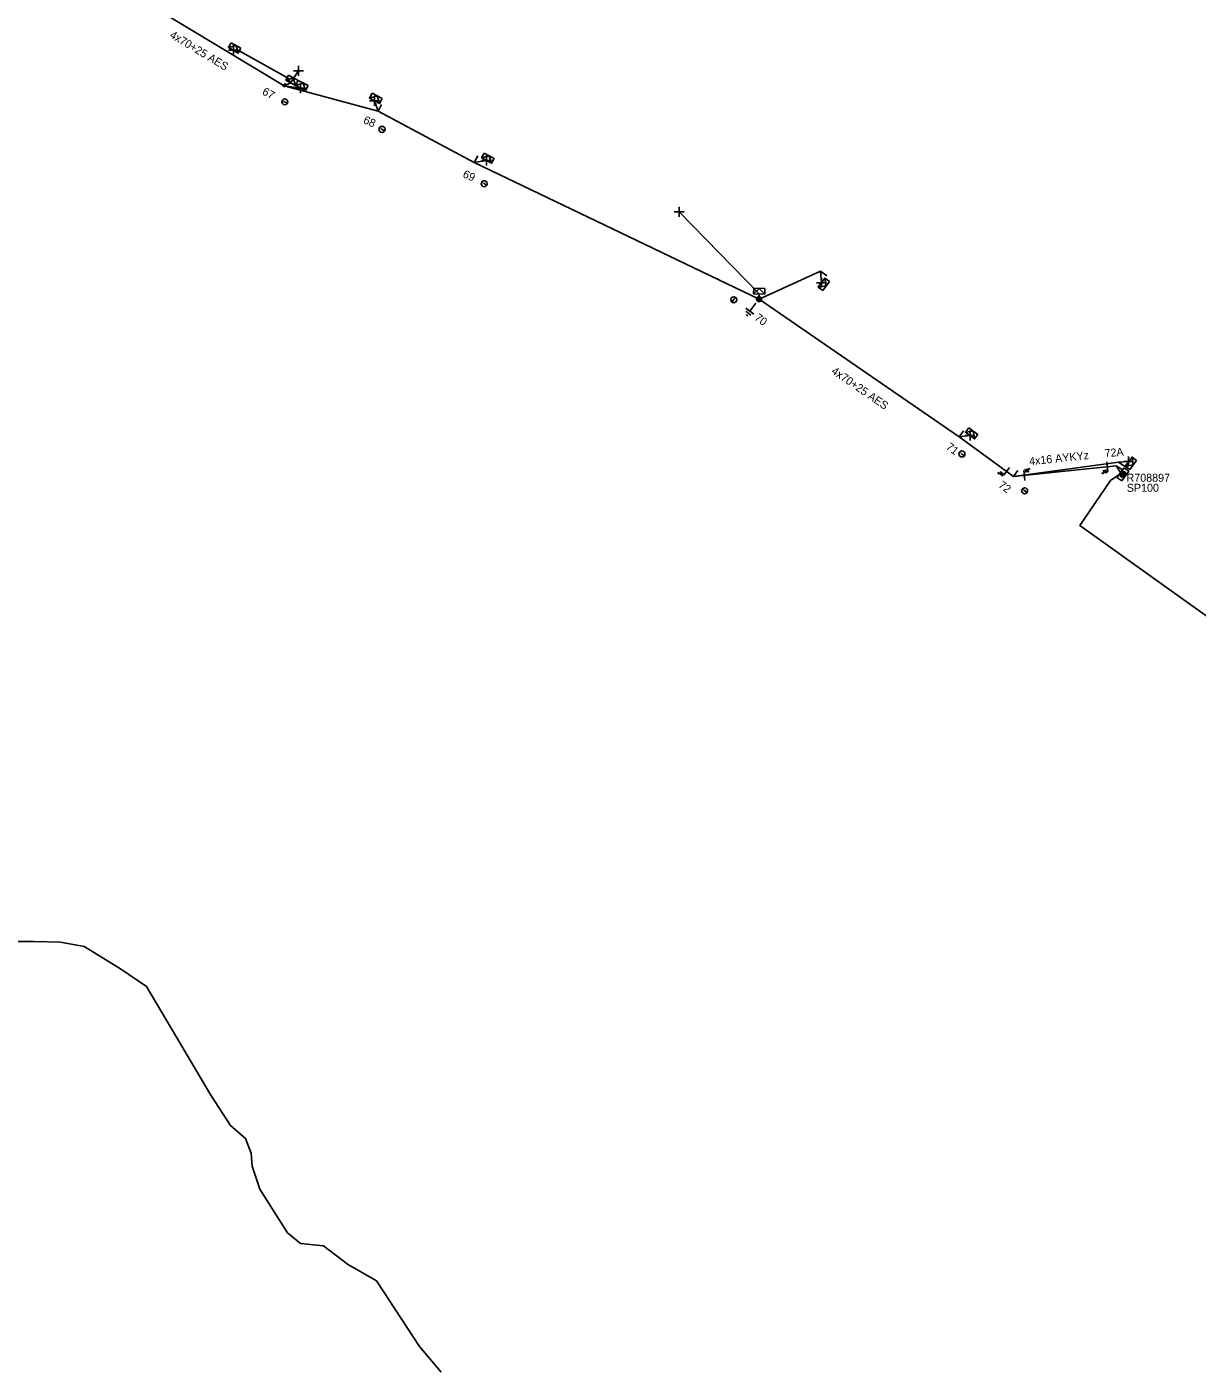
# Model space of a CAD drawing. Extents: x -540466 to -537383, y -1184038 to -1179972.
# Drawn here: x -537707.7 to -537561.4, y -1180709.3 to -1180542.1 of the extents above; entities that cross this region are included whole.
import ezdxf

# ---------------------------------------------------------------- set-up
doc = ezdxf.new("R2010")
doc.units = 0
for name, color, linetype in [('Vrstva 1', 7, 'Continuous'), ('Vrstva 10', 7, 'Continuous'), ('Vrstva 13', 7, 'Continuous'), ('Vrstva 14', 7, 'Continuous'), ('Vrstva 15', 7, 'Continuous'), ('Vrstva 18', 7, 'Continuous'), ('Vrstva 2', 7, 'Continuous'), ('Vrstva 28', 7, 'Continuous'), ('Vrstva 29', 7, 'Continuous'), ('Vrstva 30', 7, 'Continuous'), ('Vrstva 31', 7, 'Continuous'), ('Vrstva 34', 7, 'Continuous'), ('Vrstva 36', 7, 'Continuous'), ('Vrstva 4', 7, 'Continuous'), ('Vrstva 5', 7, 'Continuous'), ('Vrstva 50', 7, 'Continuous'), ('Vrstva 51', 7, 'Continuous'), ('Vrstva 52', 7, 'Continuous'), ('Vrstva 53', 7, 'Continuous'), ('Vrstva 54', 7, 'Continuous'), ('Vrstva 59', 7, 'Continuous'), ('Vrstva 8', 7, 'Continuous'), ('Vrstva 9', 7, 'Continuous')]:
    doc.layers.add(name, color=color, linetype=linetype)

# ---------------------------------------------------------------- blocks, each defined once
blk = doc.blocks.new('NN440')
at = {"layer": 'Vrstva 2'}
for points in [[(0.63, 0), (0.63, 0.06), (0.62, 0.13), (0.6, 0.19), (0.58, 0.25), (0.55, 0.31), (0.51, 0.37), (0.47, 0.42), (0.42, 0.46), (0.37, 0.51), (0.32, 0.54), (0.26, 0.57), (0.2, 0.59), (0.13, 0.61), (0.07, 0.62), (0, 0.63), (-0.06, 0.62), (-0.13, 0.61), (-0.19, 0.59), (-0.26, 0.57), (-0.31, 0.54), (-0.37, 0.51), (-0.42, 0.46), (-0.47, 0.42), (-0.51, 0.37), (-0.54, 0.31), (-0.57, 0.25), (-0.6, 0.19), (-0.62, 0.13), (-0.63, 0.06), (-0.63, 0), (-0.63, -0.07), (-0.62, -0.14), (-0.6, -0.2), (-0.57, -0.26), (-0.54, -0.32), (-0.51, -0.37), (-0.47, -0.43), (-0.42, -0.47), (-0.37, -0.51), (-0.31, -0.55), (-0.26, -0.58), (-0.19, -0.6), (-0.13, -0.62), (-0.06, -0.63), (0, -0.63), (0.07, -0.63), (0.13, -0.62), (0.2, -0.6), (0.26, -0.58), (0.32, -0.55), (0.37, -0.51), (0.42, -0.47), (0.47, -0.43), (0.51, -0.37), (0.55, -0.32), (0.58, -0.26), (0.6, -0.2), (0.62, -0.14), (0.63, -0.07), (0.63, 0)], [(-0.63, 0), (0.63, 0)], [(-0.6, -0.18), (0.57, -0.18)], [(-0.51, -0.32), (0.5, -0.32)], [(-0.37, -0.47), (0.35, -0.47)]]:
    blk.add_lwpolyline(points, dxfattribs=at)
blk = doc.blocks.new('NN840')
at = {"layer": 'Vrstva 15'}
for points in [[(0, 0.62), (0, -0.63)], [(-0.75, -0.71), (-0.75, -0.66)], [(-0.73, -0.76), (-0.75, -0.71)], [(-0.66, -0.8), (-0.73, -0.76)], [(-0.63, -0.8), (-0.66, -0.8)], [(-0.56, -0.76), (-0.63, -0.8)], [(-0.54, -0.71), (-0.56, -0.76)], [(-0.54, -0.38), (-0.54, -0.71)], [(-0.33, -0.38), (-0.33, -0.8)], [(-0.33, -0.64), (-0.13, -0.38)], [(-0.26, -0.56), (-0.09, -0.8)]]:
    blk.add_lwpolyline(points, dxfattribs=at)
blk = doc.blocks.new('NN770')
at = {"layer": 'Vrstva 10'}
for p, q in [((0, 0.19), (0, 0.26)), ((0, -0.28), (0, 0.11))]:
    blk.add_line(p, q, dxfattribs=at)
blk.add_circle((0, -0.01), 0.375, dxfattribs=at)
blk = doc.blocks.new('NN800')
at = {"layer": 'Vrstva 1'}
for points in [[(-0.44, 0.44), (0.44, -0.44)], [(-0.44, -0.44), (0.44, 0.44)]]:
    blk.add_lwpolyline(points, dxfattribs=at)
blk = doc.blocks.new('NN620')
at = {"layer": 'Vrstva 8'}
for points in [[(0.75, 0), (-0.75, 0)], [(-0.75, 0), (-0.75, -0.75)], [(0.75, -0.75), (0.75, 0)], [(-0.75, -0.75), (0.75, -0.75)], [(0.37, -0.18), (-0.38, -0.18)], [(-0.38, -0.18), (-0.38, -0.56)], [(-0.38, -0.56), (0.37, -0.56)], [(0.32, -0.23), (-0.33, -0.23)], [(-0.33, -0.23), (-0.33, -0.51)], [(-0.33, -0.51), (0.32, -0.51)], [(0.27, -0.27), (-0.28, -0.27)], [(-0.28, -0.27), (-0.28, -0.46)], [(-0.28, -0.46), (0.27, -0.46)], [(0.23, -0.32), (-0.23, -0.32)], [(-0.23, -0.32), (-0.23, -0.42)], [(-0.23, -0.42), (0.23, -0.42)], [(-0.19, -0.37), (0.19, -0.37)], [(0.23, -0.42), (0.23, -0.32)], [(0.27, -0.46), (0.27, -0.27)], [(0.32, -0.51), (0.32, -0.23)], [(0.37, -0.56), (0.37, -0.18)]]:
    blk.add_lwpolyline(points, dxfattribs=at)
blk = doc.blocks.new('NN630')
at = {"layer": 'Vrstva 9'}
for points in [[(0, -0.7), (-0.7, 0)], [(-0.7, -0.7), (-0.7, 0), (0.7, 0), (0.7, -0.7)], [(-0.7, -0.7), (0.7, -0.7)], [(0, -0.7), (0.7, 0)]]:
    blk.add_lwpolyline(points, dxfattribs=at)
blk = doc.blocks.new('NN810')
at = {"layer": 'Vrstva 14'}
for points in [[(0, -0.64), (0, -1.89)], [(0.63, -1.89), (-0.62, -1.89)], [(0.39, -2.2), (-0.4, -2.2)], [(0, -2.52), (-0.12, -2.52)], [(0.14, -2.52), (0, -2.52)]]:
    blk.add_lwpolyline(points, dxfattribs=at)
blk = doc.blocks.new('NN500')
at = {"layer": 'Vrstva 2'}
for points in [[(0, -0.24), (0.02, -0.23), (0.05, -0.23), (0.07, -0.22), (0.09, -0.22), (0.12, -0.2), (0.14, -0.19), (0.16, -0.18), (0.17, -0.16), (0.19, -0.14), (0.2, -0.12), (0.21, -0.1), (0.22, -0.07), (0.23, -0.05), (0.23, -0.02), (0.23, 0), (0.23, 0.02), (0.23, 0.05), (0.22, 0.07), (0.21, 0.1), (0.2, 0.12), (0.19, 0.14), (0.17, 0.16), (0.16, 0.17), (0.14, 0.19), (0.12, 0.2), (0.09, 0.21), (0.07, 0.22), (0.05, 0.23), (0.02, 0.23), (0, 0.23), (-0.03, 0.23), (-0.05, 0.23), (-0.07, 0.22), (-0.1, 0.21), (-0.12, 0.2), (-0.14, 0.19), (-0.16, 0.17), (-0.18, 0.16), (-0.19, 0.14), (-0.2, 0.12), (-0.22, 0.1), (-0.22, 0.07), (-0.23, 0.05), (-0.23, 0.02), (-0.24, 0), (-0.23, -0.02), (-0.23, -0.05), (-0.22, -0.07), (-0.22, -0.1), (-0.2, -0.12), (-0.19, -0.14), (-0.18, -0.16), (-0.16, -0.18), (-0.14, -0.19), (-0.12, -0.2), (-0.1, -0.22), (-0.07, -0.22), (-0.05, -0.23), (-0.03, -0.23), (0, -0.24)], [(0, -0.24), (0.02, -0.23), (0.05, -0.23), (0.07, -0.22), (0.09, -0.22), (0.12, -0.2), (0.14, -0.19), (0.16, -0.18), (0.17, -0.16), (0.19, -0.14), (0.2, -0.12), (0.21, -0.1), (0.22, -0.07), (0.23, -0.05), (0.23, -0.02), (0.23, 0), (0.23, 0.02), (0.23, 0.05), (0.22, 0.07), (0.21, 0.1), (0.2, 0.12), (0.19, 0.14), (0.17, 0.16), (0.16, 0.17), (0.14, 0.19), (0.12, 0.2), (0.09, 0.21), (0.07, 0.22), (0.05, 0.23), (0.02, 0.23), (0, 0.23), (-0.03, 0.23), (-0.05, 0.23), (-0.07, 0.22), (-0.1, 0.21), (-0.12, 0.2), (-0.14, 0.19), (-0.16, 0.17), (-0.18, 0.16), (-0.19, 0.14), (-0.2, 0.12), (-0.22, 0.1), (-0.22, 0.07), (-0.23, 0.05), (-0.23, 0.02), (-0.24, 0), (-0.23, -0.02), (-0.23, -0.05), (-0.22, -0.07), (-0.22, -0.1), (-0.2, -0.12), (-0.19, -0.14), (-0.18, -0.16), (-0.16, -0.18), (-0.14, -0.19), (-0.12, -0.2), (-0.1, -0.22), (-0.07, -0.22), (-0.05, -0.23), (-0.03, -0.23), (0, -0.24)], [(0, -0.21), (0.02, -0.2), (0.04, -0.2), (0.06, -0.2), (0.08, -0.19), (0.1, -0.18), (0.12, -0.17), (0.14, -0.15), (0.15, -0.14), (0.16, -0.12), (0.18, -0.1), (0.19, -0.08), (0.19, -0.06), (0.2, -0.04), (0.2, -0.02), (0.2, 0), (0.2, 0.02), (0.2, 0.04), (0.19, 0.06), (0.19, 0.08), (0.18, 0.1), (0.16, 0.12), (0.15, 0.14), (0.14, 0.15), (0.12, 0.17), (0.1, 0.18), (0.08, 0.19), (0.06, 0.19), (0.04, 0.2), (0.02, 0.2), (0, 0.2), (-0.02, 0.2), (-0.04, 0.2), (-0.06, 0.19), (-0.08, 0.19), (-0.1, 0.18), (-0.12, 0.17), (-0.14, 0.15), (-0.15, 0.14), (-0.17, 0.12), (-0.18, 0.1), (-0.19, 0.08), (-0.2, 0.06), (-0.2, 0.04), (-0.21, 0.02), (-0.21, 0), (-0.21, -0.02), (-0.2, -0.04), (-0.2, -0.06), (-0.19, -0.08), (-0.18, -0.1), (-0.17, -0.12), (-0.15, -0.14), (-0.14, -0.15), (-0.12, -0.17), (-0.1, -0.18), (-0.08, -0.19), (-0.06, -0.2), (-0.04, -0.2), (-0.02, -0.2), (0, -0.21)], [(0, -0.18), (0.02, -0.18), (0.04, -0.17), (0.05, -0.17), (0.07, -0.16), (0.09, -0.15), (0.1, -0.14), (0.12, -0.13), (0.13, -0.12), (0.14, -0.1), (0.15, -0.09), (0.16, -0.07), (0.17, -0.05), (0.17, -0.04), (0.17, -0.02), (0.17, 0), (0.17, 0.02), (0.17, 0.04), (0.17, 0.05), (0.16, 0.07), (0.15, 0.09), (0.14, 0.1), (0.13, 0.12), (0.12, 0.13), (0.1, 0.14), (0.09, 0.15), (0.07, 0.16), (0.05, 0.17), (0.04, 0.17), (0.02, 0.17), (0, 0.18), (-0.02, 0.17), (-0.04, 0.17), (-0.06, 0.17), (-0.07, 0.16), (-0.09, 0.15), (-0.1, 0.14), (-0.12, 0.13), (-0.13, 0.12), (-0.14, 0.1), (-0.15, 0.09), (-0.16, 0.07), (-0.17, 0.05), (-0.17, 0.04), (-0.18, 0.02), (-0.18, 0), (-0.18, -0.02), (-0.17, -0.04), (-0.17, -0.05), (-0.16, -0.07), (-0.15, -0.09), (-0.14, -0.1), (-0.13, -0.12), (-0.12, -0.13), (-0.1, -0.14), (-0.09, -0.15), (-0.07, -0.16), (-0.06, -0.17), (-0.04, -0.17), (-0.02, -0.18), (0, -0.18)], [(0, -0.15), (0.01, -0.15), (0.03, -0.14), (0.04, -0.14), (0.06, -0.13), (0.07, -0.13), (0.08, -0.12), (0.1, -0.11), (0.11, -0.1), (0.12, -0.09), (0.13, -0.07), (0.13, -0.06), (0.14, -0.05), (0.14, -0.03), (0.14, -0.02), (0.14, 0), (0.14, 0.01), (0.14, 0.03), (0.14, 0.04), (0.13, 0.06), (0.13, 0.07), (0.12, 0.09), (0.11, 0.1), (0.1, 0.11), (0.08, 0.12), (0.07, 0.13), (0.06, 0.13), (0.04, 0.14), (0.03, 0.14), (0.01, 0.14), (0, 0.15), (-0.02, 0.14), (-0.03, 0.14), (-0.05, 0.14), (-0.06, 0.13), (-0.07, 0.13), (-0.09, 0.12), (-0.1, 0.11), (-0.11, 0.1), (-0.12, 0.09), (-0.13, 0.07), (-0.13, 0.06), (-0.14, 0.04), (-0.14, 0.03), (-0.15, 0.01), (-0.15, 0), (-0.15, -0.02), (-0.14, -0.03), (-0.14, -0.05), (-0.13, -0.06), (-0.13, -0.07), (-0.12, -0.09), (-0.11, -0.1), (-0.1, -0.11), (-0.09, -0.12), (-0.07, -0.13), (-0.06, -0.13), (-0.05, -0.14), (-0.03, -0.14), (-0.02, -0.15), (0, -0.15)], [(0, -0.12), (0.01, -0.12), (0.02, -0.11), (0.03, -0.11), (0.05, -0.11), (0.06, -0.1), (0.07, -0.09), (0.08, -0.09), (0.09, -0.08), (0.09, -0.07), (0.1, -0.06), (0.11, -0.05), (0.11, -0.04), (0.11, -0.02), (0.11, -0.01), (0.12, 0), (0.11, 0.01), (0.11, 0.02), (0.11, 0.04), (0.11, 0.05), (0.1, 0.06), (0.09, 0.07), (0.09, 0.08), (0.08, 0.09), (0.07, 0.09), (0.06, 0.1), (0.05, 0.11), (0.03, 0.11), (0.02, 0.11), (0.01, 0.12), (0, 0.12), (-0.01, 0.12), (-0.03, 0.11), (-0.04, 0.11), (-0.05, 0.11), (-0.06, 0.1), (-0.07, 0.09), (-0.08, 0.09), (-0.09, 0.08), (-0.1, 0.07), (-0.1, 0.06), (-0.11, 0.05), (-0.11, 0.04), (-0.12, 0.02), (-0.12, 0.01), (-0.12, 0), (-0.12, -0.01), (-0.12, -0.02), (-0.11, -0.04), (-0.11, -0.05), (-0.1, -0.06), (-0.1, -0.07), (-0.09, -0.08), (-0.08, -0.09), (-0.07, -0.09), (-0.06, -0.1), (-0.05, -0.11), (-0.04, -0.11), (-0.03, -0.11), (-0.01, -0.12), (0, -0.12)], [(0, -0.09), (0.01, -0.09), (0.02, -0.09), (0.03, -0.08), (0.03, -0.08), (0.04, -0.08), (0.05, -0.07), (0.06, -0.07), (0.06, -0.06), (0.07, -0.05), (0.07, -0.04), (0.08, -0.04), (0.08, -0.03), (0.08, -0.02), (0.09, -0.01), (0.09, 0), (0.09, 0.01), (0.08, 0.02), (0.08, 0.03), (0.08, 0.03), (0.07, 0.04), (0.07, 0.05), (0.06, 0.06), (0.06, 0.06), (0.05, 0.07), (0.04, 0.07), (0.03, 0.08), (0.03, 0.08), (0.02, 0.08), (0.01, 0.09), (0, 0.09), (-0.01, 0.09), (-0.02, 0.08), (-0.03, 0.08), (-0.04, 0.08), (-0.04, 0.07), (-0.05, 0.07), (-0.06, 0.06), (-0.07, 0.06), (-0.07, 0.05), (-0.08, 0.04), (-0.08, 0.03), (-0.08, 0.03), (-0.09, 0.02), (-0.09, 0.01), (-0.09, 0), (-0.09, -0.01), (-0.09, -0.02), (-0.08, -0.03), (-0.08, -0.04), (-0.08, -0.04), (-0.07, -0.05), (-0.07, -0.06), (-0.06, -0.07), (-0.05, -0.07), (-0.04, -0.08), (-0.04, -0.08), (-0.03, -0.08), (-0.02, -0.09), (-0.01, -0.09), (0, -0.09)], [(0, -0.06), (0, -0.06), (0.01, -0.06), (0.02, -0.05), (0.02, -0.05), (0.03, -0.05), (0.03, -0.05), (0.04, -0.04), (0.04, -0.04), (0.05, -0.03), (0.05, -0.03), (0.05, -0.02), (0.05, -0.02), (0.05, -0.01), (0.06, -0.01), (0.06, 0), (0.06, 0.01), (0.05, 0.01), (0.05, 0.02), (0.05, 0.02), (0.05, 0.03), (0.05, 0.03), (0.04, 0.04), (0.04, 0.04), (0.03, 0.05), (0.03, 0.05), (0.02, 0.05), (0.02, 0.05), (0.01, 0.06), (0, 0.06), (0, 0.06), (-0.01, 0.06), (-0.01, 0.06), (-0.02, 0.05), (-0.02, 0.05), (-0.03, 0.05), (-0.03, 0.05), (-0.04, 0.04), (-0.04, 0.04), (-0.05, 0.03), (-0.05, 0.03), (-0.05, 0.02), (-0.06, 0.02), (-0.06, 0.01), (-0.06, 0.01), (-0.06, 0), (-0.06, -0.01), (-0.06, -0.01), (-0.06, -0.02), (-0.05, -0.02), (-0.05, -0.03), (-0.05, -0.03), (-0.04, -0.04), (-0.04, -0.04), (-0.03, -0.05), (-0.03, -0.05), (-0.02, -0.05), (-0.02, -0.05), (-0.01, -0.06), (-0.01, -0.06), (0, -0.06)], [(0, -0.03), (0, -0.03), (0, -0.03), (0.01, -0.03), (0.01, -0.03), (0.01, -0.02), (0.02, -0.02), (0.02, -0.02), (0.02, -0.02), (0.02, -0.02), (0.02, -0.01), (0.02, -0.01), (0.03, -0.01), (0.03, -0.01), (0.03, 0), (0.03, 0), (0.03, 0), (0.03, 0.01), (0.03, 0.01), (0.02, 0.01), (0.02, 0.01), (0.02, 0.02), (0.02, 0.02), (0.02, 0.02), (0.02, 0.02), (0.01, 0.02), (0.01, 0.02), (0.01, 0.03), (0, 0.03), (0, 0.03), (0, 0.03), (0, 0.03), (-0.01, 0.03), (-0.01, 0.03), (-0.01, 0.02), (-0.02, 0.02), (-0.02, 0.02), (-0.02, 0.02), (-0.02, 0.02), (-0.02, 0.02), (-0.03, 0.01), (-0.03, 0.01), (-0.03, 0.01), (-0.03, 0.01), (-0.03, 0), (-0.03, 0), (-0.03, 0), (-0.03, -0.01), (-0.03, -0.01), (-0.03, -0.01), (-0.03, -0.01), (-0.02, -0.02), (-0.02, -0.02), (-0.02, -0.02), (-0.02, -0.02), (-0.02, -0.02), (-0.01, -0.03), (-0.01, -0.03), (-0.01, -0.03), (0, -0.03), (0, -0.03)], [(0.23, 0), (0.7, 0)]]:
    blk.add_lwpolyline(points, dxfattribs=at)
blk = doc.blocks.new('NN510')
at = {"layer": 'Vrstva 2'}
blk.add_lwpolyline([(0, 0), (0, 0.94)], dxfattribs=at)

msp = doc.modelspace()

# ---------------------------------------------------------------- linework, layer by layer
at = {"layer": 'Vrstva 4'}
msp.add_lwpolyline([(-537675.51, -1180549.49), (-537674.7, -1180549.13)], dxfattribs=at)
at = {"layer": 'Vrstva 5'}
msp.add_lwpolyline([(-537655.89, -1180710.2), (-537658.59, -1180707.01), (-537663.98, -1180698.82), (-537667.6, -1180696.73), (-537670.58, -1180694.42), (-537673.47, -1180694.14), (-537675.09, -1180692.79), (-537678.56, -1180687.36), (-537679.5, -1180684.49), (-537679.62, -1180682.84), (-537680.35, -1180681.01), (-537682.22, -1180679.41), (-537684.65, -1180675.6), (-537692.7, -1180662.05), (-537695.95, -1180659.82), (-537700.51, -1180657.04), (-537703.47, -1180656.49), (-537706.77, -1180656.42), (-537709.99, -1180656.4), (-537711.42, -1180656.82), (-537714.2, -1180656.56), (-537714.2, -1180656.46)], dxfattribs=at)
at = {"layer": 'Vrstva 50'}
msp.add_lwpolyline([(-537694.26, -1180538.2), (-537691.62, -1180539.79), (-537675.51, -1180549.49), (-537663.76, -1180552.68), (-537651.75, -1180559.09), (-537616.15, -1180576.16), (-537591.14, -1180593.38), (-537584.36, -1180598.33)], dxfattribs=at)
at = {"layer": 'Vrstva 52'}
for points in [[(-537584.36, -1180598.33), (-537571.53, -1180596.98), (-537570.96, -1180597.82)], [(-537571.07, -1180598.02), (-537572.23, -1180598.8), (-537576.04, -1180604.43), (-537555.32, -1180619.26), (-537552.54, -1180615.33), (-537553.38, -1180614.42)]]:
    msp.add_lwpolyline(points, dxfattribs=at)
at = {"layer": 'Vrstva 54'}
for points in [[(-537675.51, -1180549.49), (-537673.46, -1180549.79)], [(-537663.76, -1180552.68), (-537664.22, -1180551.39)], [(-537651.75, -1180559.09), (-537650.21, -1180558.85)], [(-537591.14, -1180593.38), (-537589.78, -1180593.21)], [(-537584.36, -1180598.33), (-537571.2, -1180596.51), (-537569.95, -1180596.46)]]:
    msp.add_lwpolyline(points, dxfattribs=at)
at = {"layer": 'Vrstva 59'}
for points in [[(-537674.7, -1180549.13), (-537675.09, -1180548.5), (-537681.04, -1180545.16), (-537681.85, -1180545.07)], [(-537674.7, -1180549.13), (-537673.71, -1180547.63)], [(-537616.13, -1180575.51), (-537626.12, -1180565.25)]]:
    msp.add_lwpolyline(points, dxfattribs=at)
at = {"layer": 'Vrstva 8'}
for points in [[(-537616.15, -1180576.16), (-537608.45, -1180572.67), (-537608.33, -1180574.09)], [(-537616.15, -1180576.16), (-537616.13, -1180575.51)]]:
    msp.add_lwpolyline(points, dxfattribs=at)

# ---------------------------------------------------------------- block references
at = {"layer": 'Vrstva 13', "xscale": 0.5, "yscale": 0.5}
for name, p, rotation in [('NN500', (-537675.51, -1180549.49), 64.81699996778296), ('NN440', (-537616.15, -1180576.16), -34.54923335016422)]:
    msp.add_blockref(name, p, dxfattribs=dict(at, rotation=rotation))
at = {"layer": 'Vrstva 13'}
for p, rotation in [((-537663.76, -1180552.68), -27.931052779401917), ((-537651.75, -1180559.09), -28.45128056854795), ((-537608.45, -1180572.67), -126.34501949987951), ((-537591.14, -1180593.38), -36.332614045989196), ((-537571.2, -1180596.51), -126.67042216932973), ((-537584.36, -1180598.33), -36.33261389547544), ((-537571.53, -1180596.98), -122.1310999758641)]:
    msp.add_blockref('NN510', p, dxfattribs=dict(at, rotation=rotation))
at = {"layer": 'Vrstva 15', "rotation": -37.33293883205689}
msp.add_blockref('NN810', (-537616.15, -1180576.16), dxfattribs=at)
at = {"layer": 'Vrstva 18'}
for p, rotation in [((-537572.61, -1180597.09), 6.022261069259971), ((-537585.22, -1180597.7), -36.129774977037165), ((-537582.98, -1180598.19), -173.97773879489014)]:
    msp.add_blockref('NN840', p, dxfattribs=dict(at, rotation=rotation))
at = {"layer": 'Vrstva 28', "rotation": 53.32957783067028}
msp.add_blockref('NN620', (-537570.96, -1180597.82), dxfattribs=at)
at = {"layer": 'Vrstva 31'}
for p, rotation in [((-537681.85, -1180545.07), 151.06310566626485), ((-537674.7, -1180549.13), 150.88483893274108), ((-537673.46, -1180549.79), 152.96438056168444), ((-537664.22, -1180551.39), 152.06894722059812), ((-537650.21, -1180558.85), 151.5487195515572), ((-537616.13, -1180575.51), 178.88398976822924), ((-537608.33, -1180574.1), 53.65498055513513), ((-537589.78, -1180593.21), 143.66738606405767), ((-537569.95, -1180596.46), 53.32957783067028)]:
    msp.add_blockref('NN630', p, dxfattribs=dict(at, rotation=rotation))
at = {"layer": 'Vrstva 34'}
for p, rotation in [((-537681.85, -1180545.07), 45), ((-537673.71, -1180547.63), 45), ((-537673.46, -1180549.79), 45), ((-537664.22, -1180551.39), 44.99999995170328), ((-537650.21, -1180558.85), 45), ((-537626.12, -1180565.25), 45), ((-537608.33, -1180574.1), 45), ((-537589.78, -1180593.21), 45), ((-537569.95, -1180596.46), 45)]:
    msp.add_blockref('NN800', p, dxfattribs=dict(at, rotation=rotation))
at = {"layer": 'Vrstva 36'}
for p, rotation in [((-537675.43, -1180551.5), 64.82813329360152), ((-537663.28, -1180554.94), 62.01378053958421), ((-537650.51, -1180561.73), 61.521244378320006), ((-537619.3, -1180576.23), -32.949213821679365), ((-537590.8, -1180595.49), 53.68041948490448), ((-537582.96, -1180600.1), 53.68041948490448)]:
    msp.add_blockref('NN770', p, dxfattribs=dict(at, rotation=rotation))

# ---------------------------------------------------------------- texts
at = {"layer": 'Vrstva 14'}
for s, rotation, p in [('67', 331.318, (-537678.34, -1180550.52)), ('68', 336.288, (-537665.7, -1180554.13)), ('69', 335.165, (-537653.27, -1180560.87)), ('70', 322.761, (-537616.79, -1180578.65)), ('71', 323.196, (-537592.86, -1180594.8)), ('72A', 5.575, (-537572.91, -1180595.93)), ('72', 323.328, (-537586.32, -1180599.57))]:
    msp.add_text(s, height=1, rotation=rotation, dxfattribs=at).set_placement(p)
at = {"layer": 'Vrstva 29'}
msp.add_text('R708897', height=1, dxfattribs=at).set_placement((-537570.21, -1180598.97))
at = {"layer": 'Vrstva 30'}
msp.add_text('SP100', height=1, dxfattribs=at).set_placement((-537570.18, -1180600.23))
at = {"layer": 'Vrstva 51'}
for rotation, p in [(328.958, (-537689.9, -1180543.41)), (325.451, (-537607.2, -1180585.36))]:
    msp.add_text('4x70+25 AES', height=1, rotation=rotation, dxfattribs=at).set_placement(p)
at = {"layer": 'Vrstva 53'}
msp.add_text('4x16 AYKYz', height=1, rotation=6.022, dxfattribs=at).set_placement((-537582.34, -1180596.92))

doc.saveas('drawing.dxf')
